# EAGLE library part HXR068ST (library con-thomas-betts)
THOMAS&BETTS
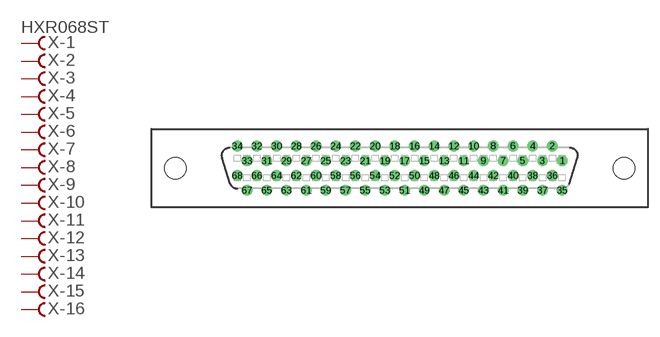
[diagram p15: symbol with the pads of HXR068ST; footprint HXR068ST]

Designator prefix X; gates -1=FV -2=F -3=F -4=F -5=F -6=F -7=F -8=F -9=F -10=F -11=F -12=F -13=F -14=F -15=F -16=F -17=F -18=F -19=F -20=F -21=F -22=F -23=F -24=F -25=F -26=F -27=F -28=F -29=F -30=F -31=F -32=F -33=F -34=F -35=F -36=F -37=F -38=F -39=F -40=F -41=F -42=F -43=F -44=F -45=F -46=F -47=F -48=F -49=F -50=F -51=F -52=F -53=F -54=F -55=F -56=F -57=F -58=F -59=F -60=F -61=F -62=F -63=F -64=F -65=F -66=F -67=F -68=F

## HXR068ST (OC_FARNELL: unknown; OC_NEWARK: unknown)  [HXR068ST]
1  -1:F  pas
2  -2:F  pas
3  -3:F  pas
4  -4:F  pas
5  -5:F  pas
6  -6:F  pas
7  -7:F  pas
8  -8:F  pas
9  -9:F  pas
10  -10:F  pas
11  -11:F  pas
12  -12:F  pas
13  -13:F  pas
14  -14:F  pas
15  -15:F  pas
16  -16:F  pas
17  -17:F  pas
18  -18:F  pas
19  -19:F  pas
20  -20:F  pas
21  -21:F  pas
22  -22:F  pas
23  -23:F  pas
24  -24:F  pas
25  -25:F  pas
26  -26:F  pas
27  -27:F  pas
28  -28:F  pas
29  -29:F  pas
30  -30:F  pas
31  -31:F  pas
32  -32:F  pas
33  -33:F  pas
34  -34:F  pas
35  -35:F  pas
36  -36:F  pas
37  -37:F  pas
38  -38:F  pas
39  -39:F  pas
40  -40:F  pas
41  -41:F  pas
42  -42:F  pas
43  -43:F  pas
44  -44:F  pas
45  -45:F  pas
46  -46:F  pas
47  -47:F  pas
48  -48:F  pas
49  -49:F  pas
50  -50:F  pas
51  -51:F  pas
52  -52:F  pas
53  -53:F  pas
54  -54:F  pas
55  -55:F  pas
56  -56:F  pas
57  -57:F  pas
58  -58:F  pas
59  -59:F  pas
60  -60:F  pas
61  -61:F  pas
62  -62:F  pas
63  -63:F  pas
64  -64:F  pas
65  -65:F  pas
66  -66:F  pas
67  -67:F  pas
68  -68:F  pas

## Footprint HXR068ST (pad centres in mm)
THOMAS&BETTS HFR068ST29xx, HHR068ST29xx
drill 0.864 octagon: 1 20.955,0.953
drill 0.864 round: 2 19.685,2.857; 3 18.415,0.953; 4 17.145,2.857; 5 15.875,0.953; 6 14.605,2.857; 7 13.335,0.953; 8 12.065,2.857; 9 10.795,0.953; 10 9.525,2.857; 11 8.255,0.953; 12 6.985,2.857; 13 5.715,0.953; 14 4.445,2.857; 15 3.175,0.953; 16 1.905,2.857; 17 0.635,0.953; 18 -0.635,2.857; 19 -1.905,0.953; 20 -3.175,2.857; 21 -4.445,0.953; 22 -5.715,2.857; 23 -6.985,0.953; 24 -8.255,2.857; 25 -9.525,0.953; 26 -10.795,2.857; 27 -12.065,0.953; 28 -13.335,2.857; 29 -14.605,0.953; 30 -15.875,2.857; 31 -17.145,0.953; 32 -18.415,2.857; 33 -19.685,0.953; 34 -20.955,2.857; 35 20.955,-2.857; 36 19.685,-0.953; 37 18.415,-2.857; 38 17.145,-0.953; 39 15.875,-2.857; 40 14.605,-0.953; 41 13.335,-2.857; 42 12.065,-0.953; 43 10.795,-2.857; 44 9.525,-0.953; 45 8.255,-2.857; 46 6.985,-0.953; 47 5.715,-2.857; 48 4.445,-0.953; 49 3.175,-2.857; 50 1.905,-0.953; 51 0.635,-2.857; 52 -0.635,-0.953; 53 -1.905,-2.857; 54 -3.175,-0.953; 55 -4.445,-2.857; 56 -5.715,-0.953; 57 -6.985,-2.857; 58 -8.255,-0.953; 59 -9.525,-2.857; 60 -10.795,-0.953; 61 -12.065,-2.857; 62 -13.335,-0.953; 63 -14.605,-2.857; 64 -15.875,-0.953; 65 -17.145,-2.857; 66 -18.415,-0.953; 67 -19.685,-2.857; 68 -20.955,-0.953
hole 2.769 at 28.956,0.013
hole 2.769 at -28.956,0.013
